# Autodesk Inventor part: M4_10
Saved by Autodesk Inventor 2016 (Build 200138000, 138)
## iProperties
Created: 2016-03
Part Number: M4_10
Material: Generic
Document SubType Name: Modeling
Designer: bongo_000
Density: 1 g/cm^3
Appearance: Default
Author: bongo_000
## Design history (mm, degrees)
feature "CUT-EXTRUDE3"
body "Solid1"
